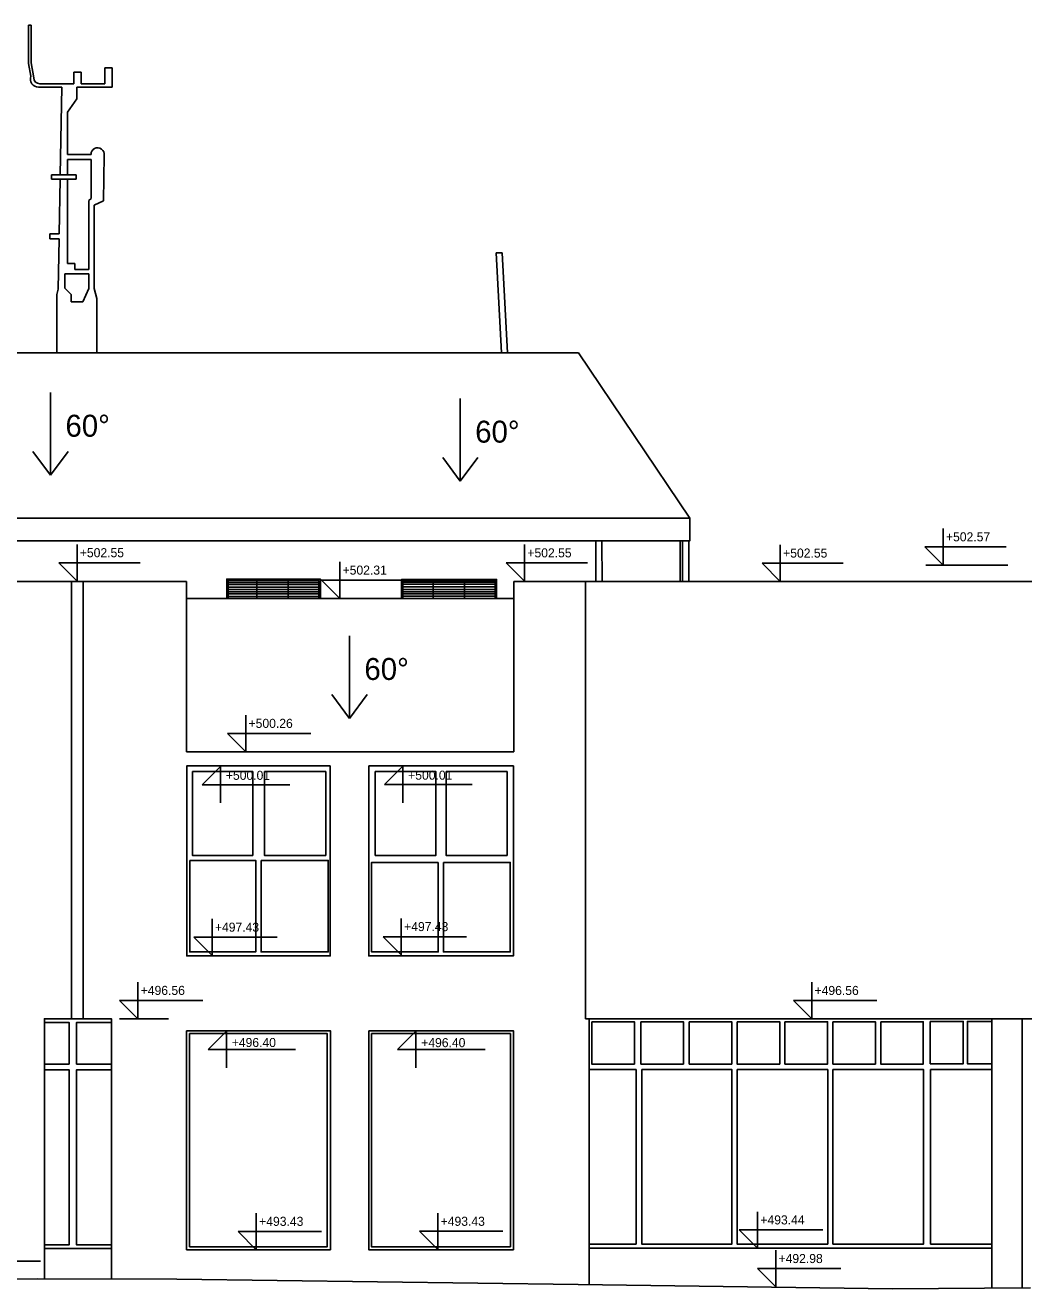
# Model space of a CAD drawing. Extents: x 3.3 to 94, y 492.8 to 514.5.
# Drawn here: x 54.56 to 68.21, y 492.89 to 510.15 of the extents above; entities that cross this region are included whole.
import ezdxf

# ---------------------------------------------------------------- set-up
doc = ezdxf.new("R2010")
doc.units = 0
for name, color, linetype in [('antena', 7, 'Continuous'), ('okap', 7, 'Continuous'), ('okna', 7, 'Continuous'), ('strecha_sikma', 7, 'Continuous'), ('teren', 7, 'Continuous'), ('vyustky_vzduchotechniky', 7, 'Continuous'), ('zakl_tenka', 7, 'Continuous'), ('znaceni', 7, 'Continuous')]:
    doc.layers.add(name, color=color, linetype=linetype)

msp = doc.modelspace()

# ---------------------------------------------------------------- linework, layer by layer
at = {"layer": 'antena'}
for p, q in [((54.609, 509.63), (54.609, 510.15)), ((54.609, 510.15), (54.644, 510.15)), ((54.644, 510.15), (54.644, 509.635)), ((54.64, 509.453), (54.609, 509.63)), ((54.644, 509.635), (54.68, 509.433)), ((55.329, 509.51), (55.229, 509.51)), ((55.229, 509.51), (55.229, 509.35)), ((55.329, 509.35), (55.329, 509.51)), ((55.749, 509.57), (55.649, 509.57)), ((55.649, 509.57), (55.649, 509.35)), ((55.749, 509.57), (55.749, 509.305)), ((55.229, 509.35), (54.762, 509.35)), ((55.649, 509.35), (55.329, 509.35)), ((55.062, 509.305), (54.743, 509.305)), ((55.062, 509.305), (55.042, 508.106)), ((55.269, 509.145), (55.142, 508.965)), ((55.749, 509.305), (55.269, 509.305)), ((55.269, 509.305), (55.269, 509.145)), ((55.142, 508.965), (55.142, 508.385)), ((55.142, 508.385), (55.462, 508.385)), ((55.462, 508.314), (55.142, 508.314)), ((55.142, 508.314), (55.142, 508.106)), ((55.462, 507.783), (55.462, 508.314)), ((55.641, 508.371), (55.631, 507.751)), ((55.26, 508.106), (54.92, 508.106)), ((54.92, 508.106), (54.92, 508.046)), ((55.26, 508.046), (55.26, 508.106)), ((54.92, 508.046), (55.26, 508.046)), ((55.04, 508.046), (55.027, 507.298)), ((55.142, 508.046), (55.142, 506.894)), ((55.433, 507.754), (55.462, 507.783)), ((55.433, 506.814), (55.433, 507.754)), ((55.631, 507.751), (55.504, 507.692)), ((55.504, 507.692), (55.504, 507.512)), ((55.504, 507.512), (55.504, 506.552)), ((55.027, 507.298), (54.897, 507.298)), ((54.897, 507.298), (54.897, 507.233)), ((54.897, 507.233), (55.026, 507.233)), ((55.026, 507.233), (55.014, 506.546)), ((61.08, 507.04), (61, 507.04)), ((61, 507.04), (61.072, 505.676)), ((61.08, 507.04), (61.152, 505.676)), ((55.104, 506.558), (55.104, 506.753)), ((55.433, 506.753), (55.104, 506.753)), ((55.142, 506.894), (55.242, 506.894)), ((55.242, 506.894), (55.242, 506.814)), ((55.242, 506.814), (55.433, 506.814)), ((55.433, 506.753), (55.433, 506.554)), ((55.189, 506.473), (55.104, 506.558)), ((55.433, 506.554), (55.349, 506.373)), ((55.504, 506.552), (55.54, 506.417)), ((55.014, 506.546), (54.994, 506.469)), ((54.994, 506.469), (54.994, 505.676)), ((55.189, 506.373), (55.189, 506.473)), ((55.54, 506.417), (55.54, 505.676)), ((55.349, 506.373), (55.189, 506.373))]:
    msp.add_line(p, q, dxfattribs=at)
for centre, radius, start, end in [((54.743, 509.415), 0.11, 160, 270), ((54.762, 509.433), 0.0823, 180, 270), ((55.552, 508.385), 0.09, 351.0217, 180)]:
    msp.add_arc(centre, radius, start, end, dxfattribs=at)
at = {"layer": 'okap'}
msp.add_lwpolyline([(63.644, 503.415), (46.838, 503.415), (46.838, 503.105), (63.644, 503.105)], close=True, dxfattribs=at)
for points in [[(62.361, 503.105), (62.361, 502.549)], [(62.446, 502.549), (62.442, 503.105)], [(63.545, 503.105), (63.545, 502.549)], [(63.632, 502.549), (63.632, 503.105)]]:
    msp.add_lwpolyline(points, dxfattribs=at)
at = {"layer": 'okna'}
for points in [[(56.848, 499.953), (57.672, 499.953), (57.672, 498.807), (56.848, 498.807)], [(57.832, 499.953), (58.67, 499.953), (58.67, 498.807), (57.832, 498.807)], [(59.346, 499.953), (60.175, 499.953), (60.175, 498.807), (59.346, 498.807)], [(60.315, 499.953), (61.147, 499.953), (61.147, 498.807), (60.315, 498.807)], [(56.811, 498.738), (57.714, 498.738), (57.714, 497.487), (56.811, 497.487)], [(57.787, 498.738), (58.704, 498.738), (58.704, 497.487), (57.787, 497.487)], [(60.208, 498.71), (59.296, 498.71), (59.296, 497.487), (60.208, 497.487)], [(60.277, 498.71), (61.191, 498.71), (61.191, 497.487), (60.277, 497.487)], [(66.93, 496.538), (67.382, 496.538), (67.382, 495.959), (66.93, 495.959)], [(56.808, 496.371), (58.691, 496.371), (58.691, 493.459), (56.808, 493.459)], [(59.294, 496.371), (61.192, 496.371), (61.192, 493.459), (59.294, 493.459)], [(62.305, 496.534), (62.887, 496.534), (62.887, 495.955), (62.305, 495.955)], [(62.976, 496.534), (63.557, 496.534), (63.557, 495.955), (62.976, 495.955)], [(63.636, 496.534), (64.217, 496.534), (64.217, 495.955), (63.636, 495.955)], [(64.291, 496.534), (64.873, 496.534), (64.873, 495.955), (64.291, 495.955)], [(64.945, 496.534), (65.527, 496.534), (65.527, 495.955), (64.945, 495.955)], [(65.599, 496.534), (66.181, 496.534), (66.181, 495.955), (65.599, 495.955)], [(66.253, 496.534), (66.834, 496.534), (66.834, 495.955), (66.253, 495.955)], [(62.987, 495.881), (64.219, 495.881), (64.219, 493.495), (62.987, 493.495)], [(64.29, 495.881), (65.53, 495.881), (65.53, 493.495), (64.29, 493.495)], [(65.599, 495.881), (66.84, 495.881), (66.84, 493.495), (65.599, 493.495)]]:
    msp.add_lwpolyline(points, close=True, dxfattribs=at)
for points in [[(67.771, 495.959), (67.439, 495.959), (67.439, 496.538), (67.771, 496.538)], [(67.771, 496.538), (67.441, 496.538)], [(54.825, 496.524), (55.162, 496.524), (55.162, 495.955), (54.825, 495.955)], [(55.74, 495.955), (55.264, 495.955), (55.264, 496.524), (55.74, 496.524)], [(54.825, 493.483), (55.162, 493.483), (55.162, 495.878), (54.825, 495.878)], [(55.74, 493.483), (55.264, 493.483), (55.264, 495.878), (55.74, 495.878)], [(62.27, 493.495), (62.91, 493.495), (62.91, 495.881), (62.27, 495.881)], [(67.771, 493.495), (66.934, 493.495), (66.934, 495.881), (67.771, 495.881)]]:
    msp.add_lwpolyline(points, dxfattribs=at)
at = {"layer": 'strecha_sikma'}
for p, q in [((62.124, 505.676), (48.184, 505.676)), ((63.644, 503.415), (62.124, 505.676)), ((63.644, 503.415), (46.835, 503.415)), ((61.242, 502.315), (56.766, 502.315)), ((61.242, 500.224), (56.766, 500.224))]:
    msp.add_line(p, q, dxfattribs=at)
at = {"layer": 'teren'}
for p, q in [((54.731, 493.02), (50.487, 493.004)), ((56.636, 493.016), (54.731, 493.02)), ((62.117, 492.943), (56.636, 493.016)), ((66.412, 492.885), (62.117, 492.943)), ((68.298, 492.896), (66.412, 492.885))]:
    msp.add_line(p, q, dxfattribs=at)
at = {"layer": 'vyustky_vzduchotechniky'}
for p, q in [((57.335, 502.537), (58.574, 502.537)), ((57.335, 502.51), (58.574, 502.51)), ((57.335, 502.474), (58.574, 502.474)), ((57.335, 502.44), (58.574, 502.44)), ((57.73, 502.564), (57.73, 502.315)), ((58.156, 502.564), (58.156, 502.315)), ((59.722, 502.539), (60.985, 502.539)), ((59.722, 502.511), (60.985, 502.511)), ((59.722, 502.475), (60.985, 502.475)), ((59.722, 502.441), (60.985, 502.441)), ((59.722, 502.409), (60.985, 502.409)), ((60.137, 502.564), (60.137, 502.315)), ((60.565, 502.564), (60.565, 502.315)), ((57.335, 502.408), (58.574, 502.408)), ((57.335, 502.379), (58.574, 502.379)), ((57.335, 502.345), (58.574, 502.345)), ((59.722, 502.38), (60.985, 502.38)), ((59.722, 502.347), (60.985, 502.347))]:
    msp.add_line(p, q, dxfattribs=at)
for points in [[(57.317, 502.315), (57.317, 502.583), (58.596, 502.583), (58.596, 502.315)], [(58.574, 502.315), (58.574, 502.564), (57.335, 502.564), (57.335, 502.315)], [(59.705, 502.315), (59.705, 502.577), (61.005, 502.577), (61.005, 502.315)], [(59.722, 502.315), (59.722, 502.564), (60.985, 502.564), (60.985, 502.315)]]:
    msp.add_lwpolyline(points, dxfattribs=at)
at = {"layer": 'zakl_tenka'}
for p, q in [((63.511, 503.105), (63.511, 502.549)), ((56.766, 502.551), (53.781, 502.551)), ((55.194, 502.551), (55.194, 496.574)), ((55.353, 502.551), (55.353, 496.574)), ((56.766, 500.224), (56.766, 502.551)), ((68.78, 502.549), (61.242, 502.549)), ((61.242, 502.549), (61.242, 500.224)), ((62.219, 496.574), (62.219, 502.554)), ((68.185, 496.574), (62.219, 496.574)), ((62.27, 496.574), (62.27, 492.941)), ((67.771, 496.574), (67.771, 492.893)), ((68.185, 496.574), (68.185, 492.895)), ((73.409, 496.574), (68.185, 496.574)), ((54.825, 493.435), (55.74, 493.435)), ((62.27, 493.44), (67.771, 493.44))]:
    msp.add_line(p, q, dxfattribs=at)
for points in [[(58.731, 500.03), (56.77, 500.03), (56.77, 497.434), (58.731, 497.434)], [(59.257, 500.03), (61.233, 500.03), (61.233, 497.434), (59.257, 497.434)], [(56.769, 496.411), (58.733, 496.411), (58.733, 493.419), (56.769, 493.419)], [(59.258, 496.411), (61.234, 496.411), (61.234, 493.419), (59.258, 493.419)]]:
    msp.add_lwpolyline(points, close=True, dxfattribs=at)
msp.add_lwpolyline([(54.825, 493.02), (54.825, 496.574), (55.74, 496.574), (55.74, 493.018)], dxfattribs=at)
at = {"layer": 'znaceni'}
for p, q in [((54.91, 505.131), (54.91, 504.001)), ((60.508, 505.049), (60.508, 503.919)), ((54.91, 504.001), (54.669, 504.328)), ((54.91, 504.001), (55.15, 504.328)), ((60.508, 503.919), (60.268, 504.246)), ((60.508, 503.919), (60.749, 504.246)), ((67.106, 503.272), (67.106, 502.772)), ((55.271, 503.056), (55.271, 502.556)), ((61.386, 503.053), (61.386, 502.553)), ((64.881, 503.05), (64.881, 502.55)), ((67.106, 503.022), (66.856, 503.022)), ((66.856, 503.022), (67.106, 502.772)), ((67.106, 502.772), (67.106, 503.022)), ((67.106, 503.022), (67.968, 503.022)), ((55.271, 502.806), (55.021, 502.806)), ((55.021, 502.806), (55.271, 502.556)), ((55.271, 502.556), (55.271, 502.806)), ((55.271, 502.806), (56.132, 502.806)), ((58.861, 502.817), (58.861, 502.317)), ((61.386, 502.803), (61.136, 502.803)), ((61.136, 502.803), (61.386, 502.553)), ((61.386, 502.553), (61.386, 502.803)), ((61.386, 502.803), (62.247, 502.803)), ((64.881, 502.8), (64.631, 502.8)), ((64.631, 502.8), (64.881, 502.55)), ((64.881, 502.55), (64.881, 502.8)), ((64.881, 502.8), (65.742, 502.8)), ((67.989, 502.774), (66.868, 502.774)), ((58.861, 502.567), (58.611, 502.567)), ((58.611, 502.567), (58.861, 502.317)), ((58.861, 502.317), (58.861, 502.567)), ((58.861, 502.567), (59.722, 502.567)), ((58.994, 501.807), (58.994, 500.677)), ((58.994, 500.677), (58.754, 501.004)), ((58.994, 500.677), (59.235, 501.004)), ((57.576, 500.724), (57.576, 500.224)), ((57.576, 500.474), (57.326, 500.474)), ((57.326, 500.474), (57.576, 500.224)), ((57.576, 500.224), (57.576, 500.474)), ((57.576, 500.474), (58.466, 500.474)), ((56.982, 499.773), (57.232, 500.023)), ((57.232, 500.023), (57.232, 499.523)), ((57.232, 499.523), (57.232, 500.023)), ((57.232, 500.023), (57.232, 499.773)), ((59.473, 499.775), (59.723, 500.025)), ((59.723, 500.025), (59.723, 499.525)), ((59.723, 499.525), (59.723, 500.025)), ((59.723, 500.025), (59.723, 499.775)), ((57.232, 499.773), (56.982, 499.773)), ((57.232, 499.773), (56.982, 499.773)), ((57.232, 499.523), (57.232, 499.773)), ((57.232, 499.773), (58.177, 499.773)), ((57.232, 499.773), (58.177, 499.773)), ((59.723, 499.775), (59.473, 499.775)), ((59.723, 499.775), (59.473, 499.775)), ((59.723, 499.525), (59.723, 499.775)), ((59.723, 499.775), (60.669, 499.775)), ((59.723, 499.775), (60.669, 499.775)), ((57.116, 497.939), (57.116, 497.439)), ((59.702, 497.946), (59.702, 497.446)), ((57.116, 497.689), (56.866, 497.689)), ((56.866, 497.689), (57.116, 497.439)), ((57.116, 497.439), (57.116, 497.689)), ((57.116, 497.689), (58.005, 497.689)), ((59.702, 497.696), (59.452, 497.696)), ((59.452, 497.696), (59.702, 497.446)), ((59.702, 497.446), (59.702, 497.696)), ((59.702, 497.696), (60.592, 497.696)), ((56.102, 497.074), (56.102, 496.574)), ((65.31, 497.073), (65.31, 496.573)), ((56.102, 496.824), (55.852, 496.824)), ((55.852, 496.824), (56.102, 496.574)), ((56.102, 496.574), (56.102, 496.824)), ((56.102, 496.824), (56.992, 496.824)), ((65.31, 496.823), (65.06, 496.823)), ((65.06, 496.823), (65.31, 496.573)), ((65.31, 496.573), (65.31, 496.823)), ((65.31, 496.823), (66.2, 496.823)), ((55.852, 496.574), (56.519, 496.574)), ((57.062, 496.156), (57.312, 496.406)), ((57.312, 496.406), (57.312, 495.906)), ((57.312, 495.906), (57.312, 496.406)), ((57.312, 496.406), (57.312, 496.156)), ((59.651, 496.155), (59.901, 496.405)), ((59.901, 496.405), (59.901, 495.905)), ((59.901, 495.905), (59.901, 496.405)), ((59.901, 496.405), (59.901, 496.155)), ((57.312, 496.156), (57.062, 496.156)), ((57.312, 496.156), (57.062, 496.156)), ((57.312, 495.906), (57.312, 496.156)), ((57.312, 496.156), (58.258, 496.156)), ((57.312, 496.156), (58.258, 496.156)), ((59.901, 496.155), (59.651, 496.155)), ((59.901, 496.155), (59.651, 496.155)), ((59.901, 495.905), (59.901, 496.155)), ((59.901, 496.155), (60.846, 496.155)), ((59.901, 496.155), (60.846, 496.155)), ((57.721, 493.918), (57.721, 493.418)), ((60.201, 493.92), (60.201, 493.42)), ((64.57, 493.938), (64.57, 493.438)), ((57.721, 493.668), (57.471, 493.668)), ((57.471, 493.668), (57.721, 493.418)), ((57.721, 493.418), (57.721, 493.668)), ((57.721, 493.668), (58.61, 493.668)), ((60.201, 493.67), (59.951, 493.67)), ((59.951, 493.67), (60.201, 493.42)), ((60.201, 493.42), (60.201, 493.67)), ((60.201, 493.67), (61.09, 493.67)), ((64.57, 493.688), (64.32, 493.688)), ((64.32, 493.688), (64.57, 493.438)), ((64.57, 493.438), (64.57, 493.688)), ((64.57, 493.688), (65.46, 493.688)), ((53.883, 493.264), (54.772, 493.264)), ((64.818, 493.41), (64.818, 492.91)), ((64.818, 493.16), (64.568, 493.16)), ((64.568, 493.16), (64.818, 492.91)), ((64.818, 492.91), (64.818, 493.16)), ((64.818, 493.16), (65.708, 493.16))]:
    msp.add_line(p, q, dxfattribs=at)

# ---------------------------------------------------------------- texts
for s, height, p in [('60°', 0.3, (55.113, 504.528)), ('60°', 0.3, (60.712, 504.447)), ('+502.57', 0.124, (67.145, 503.098)), ('+502.55', 0.124, (55.309, 502.881)), ('+502.55', 0.124, (61.425, 502.879)), ('+502.55', 0.124, (64.92, 502.876)), ('+502.31', 0.124, (58.9, 502.643)), ('60°', 0.3, (59.198, 501.204)), ('+500.26', 0.124, (57.615, 500.549)), ('+500.01', 0.124, (57.305, 499.839)), ('+500.01', 0.124, (59.796, 499.841)), ('+497.43', 0.124, (57.155, 497.764)), ('+497.43', 0.124, (59.741, 497.772)), ('+496.56', 0.124, (56.141, 496.9)), ('+496.56', 0.124, (65.349, 496.899)), ('+496.40', 0.124, (57.385, 496.188)), ('+496.40', 0.124, (59.974, 496.186)), ('+493.43', 0.124, (57.76, 493.744)), ('+493.43', 0.124, (60.24, 493.745)), ('+493.44', 0.124, (64.609, 493.764)), ('+492.98', 0.124, (64.857, 493.236))]:
    msp.add_text(s, height=height, dxfattribs=at).set_placement(p)

doc.saveas('drawing.dxf')
